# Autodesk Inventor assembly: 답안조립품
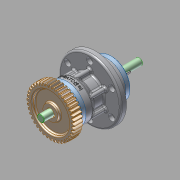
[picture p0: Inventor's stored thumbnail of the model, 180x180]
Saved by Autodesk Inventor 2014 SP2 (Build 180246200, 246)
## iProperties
Created: 2024-04
Part Number: 답안조립품
Document SubType Name: Assembly
Designer: Administrator
Author: Administrator
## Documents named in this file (10)
- C:\Users\Administrator\Desktop\740404V1009\답안조립품.iam
- C:\Users\Administrator\Desktop\740404V1009\본체.ipt
- C:\Users\Administrator\Desktop\740404V1009\가져온 구성요소\축\축.ipt
- C:\Users\Administrator\Desktop\740404V1009\가져온 구성요소\깊은 홈 볼 베어링 6204\깊은 홈 볼 베어링 6204.ipt
- C:\Users\Administrator\Desktop\740404V1009\가져온 구성요소\커버\커버.ipt
- C:\Users\Administrator\Desktop\740404V1009\가져온 구성요소\육각 소켓 머리 볼트 M4x10\육각 소켓 머리 볼트 M4x10.ipt
- C:\Users\Administrator\Desktop\740404V1009\가져온 구성요소\오일 실 20 32 5\오일 실 20 32 5.ipt
- C:\Users\Administrator\Desktop\740404V1009\가져온 구성요소\평행키 4x4x12\평행키 4x4x12.ipt
- C:\Users\Administrator\Desktop\740404V1009\가져온 구성요소\평행키 4x4x18\평행키 4x4x18.ipt
- C:\Users\Administrator\Desktop\740404V1009\가져온 구성요소\스퍼기어\스퍼기어.ipt
